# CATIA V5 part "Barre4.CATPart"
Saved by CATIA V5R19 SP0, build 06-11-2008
Part number: Barre4
Bounding box of the stored display mesh (mm): x -4.023 to 29.01, y -3.662 to 23.613, z 3.515 to 6.485
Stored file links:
  F:\IAO\Catia\Barre4.CATPart
  F:\IAO\Catia\Etau.CATProduct
  F:\IAO\Catia\Squelette_barre4.CATPart
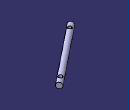
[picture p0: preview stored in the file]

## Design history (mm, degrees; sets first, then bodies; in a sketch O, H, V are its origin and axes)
Set1
  Plane1: linked copy from another document
  Point1: linked copy from another document
  Point2: linked copy from another document
  Line1: linked copy from another document
Body1 (main body)
  Sketch1 on Plane1, origin (0, 0, 5), H (1, 0, 0), V (0, 1, 0)
    line L1 (28.1113, 22.489) -> (29.0483, 21.3177)
    line L2 (29.0483, 21.3177) -> (-2.1864, -3.6701)
    line L3 (-2.1864, -3.6701) -> (-3.1235, -2.4988)
    line L4 (-3.1235, -2.4988) -> (28.1113, 22.489)
    reference projected line E1 (0, 0) -> (25, 20) from Line1
    reference projected point E2 (0, 0) from Point1
    length L2 = 40
    distance L3 E2 = 4
    length L1 = 1.5
    coincidence: L4 E1
    parallelism: L2 L4
    perpendicularity: L3 L2, L1 L2
  Shaft1: profile Sketch1, axis Sketch1.L4, angle 360
  Sketch2 on Plane1, origin (0, 0, 5), H (1, 0, 0), V (0, 1, 0)
    circle A1 centre (25, 20) radius 1
    point P1 (25, 20)
    circle A2 centre (0, 0) radius 1
    point P2 (0, 0)
    reference projected point E1 (25, 20) from Point2
    reference projected point E2 (0, 0) from Point1
    radius A2 = 1
    radius A1 = 1
    coincidence: P1 E1, P2 E2
  Pocket1: profile Sketch2, direction (0, 0, -1), length 3, mirrored extent
  Sketch3 on xy-plane, origin (0, 0, 0), H (1, 0, 0), V (0, 1, 0)
    line L1 (-6.912, 3.9139) -> (1.9771, 3.9139)
    line L2 (1.9771, 3.9139) -> (1.9771, -6.4122)
    line L3 (1.9771, -6.4122) -> (-6.912, -6.4122)
    line L4 (-6.912, -6.4122) -> (-6.912, 3.9139)
    horizontal: L1 H, L3 H
    vertical: L2 V, L4 V
  Pocket2: profile Sketch3, direction (0, 0, 1), length 4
